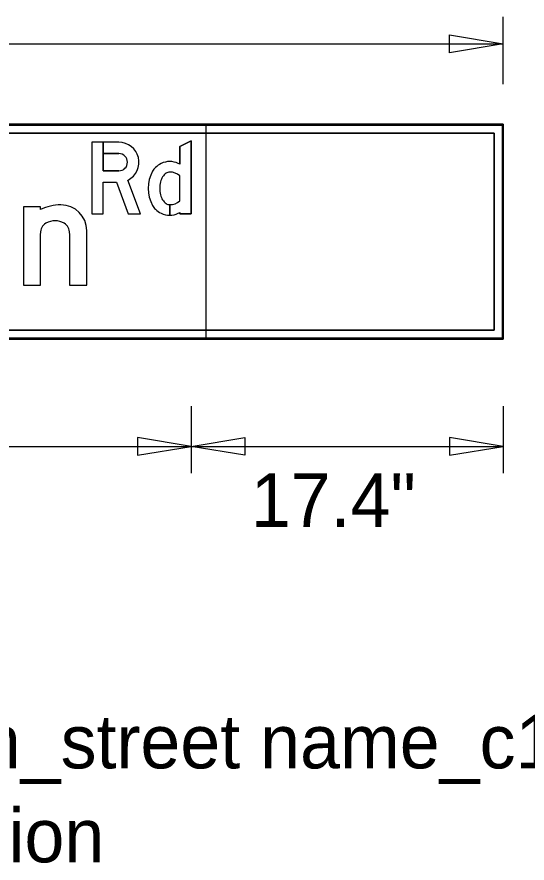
# Model space of a CAD drawing. Extents: x 1708.4 to 1771.6, y 238.3 to 283.4.
# Drawn here: x 1729.357 to 1732.208, y 249.146 to 253.875 of the extents above; entities that cross this region are included whole.
import ezdxf

# ---------------------------------------------------------------- set-up
doc = ezdxf.new("R2010")
doc.units = 0
for name, color, linetype in [('Level 11', 7, 'Continuous'), ('Level 2', 7, 'Continuous'), ('Level 3', 7, 'Continuous'), ('Level 4', 7, 'Continuous'), ('Level 5', 7, 'Continuous')]:
    doc.layers.add(name, color=color, linetype=linetype)

msp = doc.modelspace()

# ---------------------------------------------------------------- linework, layer by layer
at = {"layer": 'Level 11'}
msp.add_lwpolyline([(1730.4144, 253.275), (1732.0747, 253.275), (1732.0747, 252.075), (1730.4144, 252.075)], close=True, dxfattribs=at)
at = {"layer": 'Level 2'}
for p, q in [((1732.0748, 253.2752), (1725.2745, 253.2752)), ((1732.0748, 253.2752), (1725.2745, 253.2752)), ((1732.0748, 253.2752), (1725.2745, 253.2752)), ((1725.2795, 253.2703), (1732.0698, 253.2703)), ((1732.0698, 253.2703), (1732.0698, 252.08)), ((1732.0748, 252.075), (1732.0748, 253.2752)), ((1732.0748, 252.075), (1732.0748, 253.2752)), ((1732.0748, 252.075), (1732.0748, 253.2752)), ((1725.3245, 253.2253), (1732.0248, 253.2253)), ((1732.0248, 253.2253), (1732.0248, 252.125)), ((1729.6507, 252.6656), (1729.6507, 252.375)), ((1732.0248, 252.125), (1725.2745, 252.125)), ((1732.0698, 252.08), (1725.2745, 252.08)), ((1725.2745, 252.075), (1732.0748, 252.075)), ((1725.2745, 252.075), (1732.0748, 252.075)), ((1725.2745, 252.075), (1732.0748, 252.075))]:
    msp.add_line(p, q, dxfattribs=at)
for points in [[(1729.9267, 253.015), (1729.8387, 253.015), (1729.8387, 253.175), (1729.7747, 253.175), (1729.7747, 252.775), (1729.8387, 252.775), (1729.8387, 252.951), (1729.9139, 252.951), (1729.9785, 252.775), (1730.0467, 252.775), (1729.9775, 252.9633)], [(1729.8387, 253.175), (1729.8387, 253.111), (1729.9267, 253.111)], [(1729.9267, 253.175), (1729.8387, 253.175)], [(1730.2667, 253.0516), (1730.2667, 253.151), (1730.3307, 253.182), (1730.3307, 252.775), (1730.2667, 252.775), (1730.2667, 252.7825)], [(1730.2667, 252.847), (1730.2667, 252.987)], [(1729.4887, 252.798), (1729.4887, 252.813), (1729.3927, 252.813), (1729.3927, 252.375), (1729.4887, 252.375), (1729.4887, 252.6656)], [(1730.2107, 252.826), (1730.2107, 252.767)], [(1730.2107, 252.767), (1730.2107, 252.826)], [(1729.6507, 252.375), (1729.7467, 252.375), (1729.7467, 252.681)]]:
    msp.add_lwpolyline(points, dxfattribs=at)
for centre, radius, start, end in [((1730.1855, 252.9753), 0.08, 133.5224, 151.6141), ((1730.2205, 252.9384), 0.1309, 116.0163, 133.5224), ((1730.2107, 252.9584), 0.1086, 90, 116.0163), ((1730.2107, 252.9584), 0.1086, 63.9837, 90), ((1730.201, 252.9384), 0.1309, 59.8311, 63.9837), ((1730.2933, 252.917), 0.2026, 151.6141, 208.3859), ((1730.2286, 252.946), 0.0675, 123.9444, 148.3925), ((1730.2107, 252.9726), 0.0355, 90, 123.9444), ((1730.2107, 252.9229), 0.0852, 48.8879, 90), ((1730.3021, 252.917), 0.1474, 165.6998, 180), ((1730.257, 252.9285), 0.1009, 148.3925, 165.6998), ((1730.3021, 252.917), 0.1474, 180, 194.3002), ((1730.257, 252.9056), 0.1009, 194.3002, 211.6075), ((1730.2286, 252.8881), 0.0675, 211.6075, 236.0556), ((1730.2107, 252.9112), 0.0852, 270.0067, 311.1121), ((1729.6027, 252.5709), 0.2542, 90, 116.6491), ((1729.6027, 252.681), 0.144, 0, 90), ((1730.1855, 252.8588), 0.08, 208.3859, 226.4776), ((1730.2205, 252.8957), 0.1309, 226.4776, 243.9837), ((1730.2107, 252.8615), 0.0355, 236.0556, 270), ((1730.2107, 252.8756), 0.1086, 243.9837, 270), ((1730.2107, 252.8756), 0.1086, 270.0053, 296.0163), ((1730.201, 252.8957), 0.1309, 296.0163, 300.1689), ((1729.5548, 252.6677), 0.0661, 123.3356, 181.7567), ((1729.5697, 252.6256), 0.1099, 62.2024, 117.7976), ((1729.5847, 252.6677), 0.0661, 358.2433, 56.6644)]:
    msp.add_arc(centre, radius, start, end, dxfattribs=at)
for major_axis, start_param in [((0, 0.112), 3.613317), ((0, 0.048), 3.141593)]:
    msp.add_ellipse((1729.9267, 253.063), major_axis=major_axis, ratio=0.999993, start_param=start_param, end_param=6.283185, dxfattribs=at)
at = {"layer": 'Level 3'}
for p, q in [((1732.0748, 253.2752), (1725.2745, 253.2752)), ((1732.0748, 253.2752), (1725.2745, 253.2752)), ((1732.0748, 252.075), (1732.0748, 253.2752)), ((1732.0748, 252.075), (1732.0748, 253.2752)), ((1732.0248, 253.2253), (1725.3245, 253.2253)), ((1732.0248, 252.125), (1732.0248, 253.2253)), ((1729.6507, 252.6656), (1729.6507, 252.375)), ((1725.3245, 252.125), (1732.0248, 252.125)), ((1725.2745, 252.075), (1732.0748, 252.075)), ((1725.2745, 252.075), (1732.0748, 252.075))]:
    msp.add_line(p, q, dxfattribs=at)
for points in [[(1729.9267, 253.175), (1729.7747, 253.175), (1729.7747, 252.775), (1729.8387, 252.775), (1729.8387, 252.951), (1729.9139, 252.951), (1729.9785, 252.775), (1730.0467, 252.775), (1729.9775, 252.9633)], [(1730.2667, 252.7825), (1730.2667, 252.775), (1730.3307, 252.775), (1730.3307, 253.182), (1730.2667, 253.151), (1730.2667, 253.0516)], [(1729.9267, 253.111), (1729.8387, 253.111), (1729.8387, 253.015), (1729.9267, 253.015)], [(1730.2667, 252.847), (1730.2667, 252.987)], [(1729.4887, 252.798), (1729.4887, 252.813), (1729.3927, 252.813), (1729.3927, 252.375), (1729.4887, 252.375), (1729.4887, 252.6656)], [(1729.6507, 252.375), (1729.7467, 252.375), (1729.7467, 252.681)]]:
    msp.add_lwpolyline(points, dxfattribs=at)
for centre, radius, start, end in [((1730.1855, 252.9753), 0.08, 133.5224, 151.6141), ((1730.2205, 252.9384), 0.1309, 116.0163, 133.5224), ((1730.2107, 252.9584), 0.1086, 90, 116.0163), ((1730.2107, 252.9584), 0.1086, 63.9837, 90), ((1730.201, 252.9384), 0.1309, 59.8311, 63.9837), ((1730.2933, 252.917), 0.2026, 151.6141, 208.3859), ((1730.2286, 252.946), 0.0675, 123.9444, 148.3925), ((1730.2107, 252.9726), 0.0355, 90, 123.9444), ((1730.2107, 252.9229), 0.0852, 48.8879, 90), ((1730.3021, 252.917), 0.1474, 165.6998, 180), ((1730.257, 252.9285), 0.1009, 148.3925, 165.6998), ((1730.3021, 252.917), 0.1474, 180, 194.3002), ((1730.257, 252.9056), 0.1009, 194.3002, 211.6075), ((1730.2286, 252.8881), 0.0675, 211.6075, 236.0556), ((1730.2107, 252.9112), 0.0852, 270, 311.1121), ((1729.6027, 252.5709), 0.2542, 90, 116.6491), ((1729.6027, 252.681), 0.144, 0, 90), ((1730.1855, 252.8588), 0.08, 208.3859, 226.4776), ((1730.2205, 252.8957), 0.1309, 226.4776, 243.9837), ((1730.2107, 252.8615), 0.0355, 236.0556, 270), ((1730.2107, 252.8756), 0.1086, 243.9837, 270), ((1730.2107, 252.8756), 0.1086, 270.0053, 296.0163), ((1730.2107, 252.8756), 0.1086, 270, 270.0053), ((1730.201, 252.8957), 0.1309, 296.0163, 300.1689), ((1729.5548, 252.6677), 0.0661, 123.3356, 181.7567), ((1729.5697, 252.6256), 0.1099, 62.2024, 117.7976), ((1729.5847, 252.6677), 0.0661, 358.2433, 56.6644)]:
    msp.add_arc(centre, radius, start, end, dxfattribs=at)
for major_axis, start_param in [((0, 0.112), 3.613317), ((0, 0.048), 3.141593)]:
    msp.add_ellipse((1729.9267, 253.063), major_axis=major_axis, ratio=0.999993, start_param=start_param, end_param=6.283185, dxfattribs=at)
at = {"layer": 'Level 4'}
for p, q in [((1732.0748, 253.2752), (1725.2745, 253.2752)), ((1732.0748, 253.2752), (1725.2745, 253.2752)), ((1732.0748, 252.075), (1732.0748, 253.2752)), ((1732.0748, 252.075), (1732.0748, 253.2752)), ((1725.3245, 253.2253), (1732.0248, 253.2253)), ((1732.0248, 253.2253), (1732.0248, 252.125)), ((1729.6507, 252.6656), (1729.6507, 252.375)), ((1732.0248, 252.125), (1725.2745, 252.125)), ((1725.2745, 252.075), (1732.0748, 252.075)), ((1725.2745, 252.075), (1732.0748, 252.075))]:
    msp.add_line(p, q, dxfattribs=at)
for points in [[(1729.9267, 253.015), (1729.8387, 253.015), (1729.8387, 253.175), (1729.7747, 253.175), (1729.7747, 252.775), (1729.8387, 252.775), (1729.8387, 252.951), (1729.9139, 252.951), (1729.9785, 252.775), (1730.0467, 252.775), (1729.9775, 252.9633)], [(1729.8387, 253.175), (1729.8387, 253.111), (1729.9267, 253.111)], [(1729.9267, 253.175), (1729.8387, 253.175)], [(1730.2667, 253.0516), (1730.2667, 253.151), (1730.3307, 253.182), (1730.3307, 252.775), (1730.2667, 252.775), (1730.2667, 252.7825)], [(1730.2667, 252.847), (1730.2667, 252.987)], [(1729.4887, 252.798), (1729.4887, 252.813), (1729.3927, 252.813), (1729.3927, 252.375), (1729.4887, 252.375), (1729.4887, 252.6656)], [(1730.2107, 252.826), (1730.2107, 252.767)], [(1730.2107, 252.767), (1730.2107, 252.826)], [(1729.6507, 252.375), (1729.7467, 252.375), (1729.7467, 252.681)]]:
    msp.add_lwpolyline(points, dxfattribs=at)
for centre, radius, start, end in [((1730.1855, 252.9753), 0.08, 133.5224, 151.6141), ((1730.2205, 252.9384), 0.1309, 116.0163, 133.5224), ((1730.2107, 252.9584), 0.1086, 90, 116.0163), ((1730.2107, 252.9584), 0.1086, 63.9837, 90), ((1730.201, 252.9384), 0.1309, 59.8311, 63.9837), ((1730.2933, 252.917), 0.2026, 151.6141, 208.3859), ((1730.2286, 252.946), 0.0675, 123.9444, 148.3925), ((1730.2107, 252.9726), 0.0355, 90, 123.9444), ((1730.2107, 252.9229), 0.0852, 48.8879, 90), ((1730.3021, 252.917), 0.1474, 165.6998, 180), ((1730.257, 252.9285), 0.1009, 148.3925, 165.6998), ((1730.3021, 252.917), 0.1474, 180, 194.3002), ((1730.257, 252.9056), 0.1009, 194.3002, 211.6075), ((1730.2286, 252.8881), 0.0675, 211.6075, 236.0556), ((1730.2107, 252.9112), 0.0852, 270.0067, 311.1121), ((1729.6027, 252.5709), 0.2542, 90, 116.6491), ((1729.6027, 252.681), 0.144, 0, 90), ((1730.1855, 252.8588), 0.08, 208.3859, 226.4776), ((1730.2205, 252.8957), 0.1309, 226.4776, 243.9837), ((1730.2107, 252.8615), 0.0355, 236.0556, 270), ((1730.2107, 252.8756), 0.1086, 243.9837, 270), ((1730.2107, 252.8756), 0.1086, 270.0053, 296.0163), ((1730.201, 252.8957), 0.1309, 296.0163, 300.1689), ((1729.5548, 252.6677), 0.0661, 123.3356, 181.7567), ((1729.5697, 252.6256), 0.1099, 62.2024, 117.7976), ((1729.5847, 252.6677), 0.0661, 358.2433, 56.6644)]:
    msp.add_arc(centre, radius, start, end, dxfattribs=at)
for major_axis, start_param in [((0, 0.112), 3.613317), ((0, 0.048), 3.141593)]:
    msp.add_ellipse((1729.9267, 253.063), major_axis=major_axis, ratio=0.999993, start_param=start_param, end_param=6.283185, dxfattribs=at)
at = {"layer": 'Level 5'}
for p, q in [((1732.075, 253.5002), (1732.075, 253.8752)), ((1725.2745, 253.7253), (1732.075, 253.7253)), ((1732.075, 253.5002), (1732.075, 253.5002)), ((1730.3308, 251.7), (1730.3308, 251.325)), ((1730.3308, 251.7), (1730.3308, 251.325)), ((1732.075, 251.7), (1732.075, 251.325)), ((1732.075, 251.7), (1732.075, 251.325)), ((1725.4747, 251.475), (1730.3308, 251.475)), ((1730.3308, 251.475), (1732.075, 251.475))]:
    msp.add_line(p, q, dxfattribs=at)
for points in [[(1732.075, 253.7253), (1731.775, 253.6753), (1731.775, 253.7752)], [(1730.3308, 251.475), (1730.0308, 251.525), (1730.0308, 251.425)], [(1730.3308, 251.475), (1730.6308, 251.525), (1730.6308, 251.425)], [(1732.075, 251.475), (1731.775, 251.525), (1731.775, 251.425)]]:
    msp.add_lwpolyline(points, close=True, dxfattribs=at)

# ---------------------------------------------------------------- texts
for s, p in [('17.4"', (1730.6637, 251.025)), ('Panel Style: guide_con_street name_c1_2012.ssi', (1725.2745, 249.675)), ('M.U.T.C.D.:: 2009 Edition', (1725.2745, 249.15))]:
    msp.add_text(s, height=0.3, dxfattribs=at).set_placement(p)

doc.saveas('drawing.dxf')
